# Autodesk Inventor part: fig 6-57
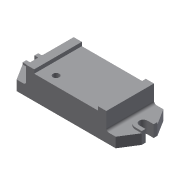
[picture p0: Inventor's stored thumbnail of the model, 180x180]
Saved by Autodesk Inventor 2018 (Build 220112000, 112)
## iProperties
Shininess: 77.0
Angle Display Precision: 2
Document Length Units: 11269
Document Angle Units: 11279
Document Time Units: 11290
Document Mass Units: 11283
Document Length Units Precision: 3
Document Angle Units Precision: 2
Created: 2001-12
Part Number: fig 6-57
Document SubType Name: Modeling
Designer: Renu Muthoo
Density: 1 g/cm^3
Material: Generic
Appearance: Default
Density: 0.0
Volumn: 0.0
Area: 0.0
PropertySet Name: Model Information
Control State: 0
Master: False
Checked Out: False
Author: Renu Muthoo
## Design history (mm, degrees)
sketch "Sketch3"
  geometry: L1 (-59.119, -24.322)-(-59.119, 19.678); L2 (-59.119, 19.678)-(-46.119, 19.678); L3 (-46.119, 19.678)-(-46.119, 13.678); L4 (-46.119, 13.678)-(55.881, 13.678); L5 (55.881, 13.678)-(55.881, 19.678); L6 (55.881, 19.678)-(68.881, 19.678); L7 (68.881, 19.678)-(68.881, -24.322); L8 (68.881, -24.322)-(-59.119, -24.322)
  constraints: 16 end point, 2 equal length
  dimensions: "d10" = 13 distance of L1.end L2.end; "d11" = 102 distance of L3.end L4.end; "d13" = 44 distance between parallel lines of L2 L8; "d14" = 6 distance of L2.end L3.end
extrude "Extrusion1" new body sketch "Sketch3" distance "d15" = 76; taper "d16" = 0 deg
sketch "Sketch4"
  geometry: L1 (0, 0)-(0, 76) reference; L2 (0, 76)-(-15, 76); L3 (-15, 76)-(-31, 50.5); L4 (-31, 50.5)-(-31, 44.5); L5 (-31, 44.5)-(-21, 44.5); L6 (-21, 31.5)-(-31, 31.5); L7 (-31, 31.5)-(-31, 25.5); L8 (-31, 25.5)-(-15, 0); L9 (-15, 0)-(0, 0); L10 (128, 76)-(0, 76) reference; L11 (0, 0)-(128, 0) reference; A1 r 6.5 centre (-21, 38) between (-21, 31.5) and (-21, 44.5)
  constraints: 16 end point, 4 equal length, 3 collinear, 3 parallel, 2 perpendicular, 2 point on circle, 2 tangent, 1 centre point
  dimensions: "d17" = 13 distance between parallel lines of L6 L5; "d18" = 25 distance of L3.end L7.end; "d19" = 10 distance of L6.start L6.end; "d20" = 15 distance of L8.end L1.start; "d21" = 16 horizontal distance of L7.end L8.end
extrude "Extrusion2" join sketch "Sketch4" distance "d22" = 16; taper "d23" = 0 deg
sketch "Sketch5"
  geometry: L1 (-159, 44.5)-(-159, 50.5) reference; L2 (-149, 44.5)-(-159, 44.5) reference; L3 (-159, 31.5)-(-149, 31.5) reference; L4 (-159, 25.5)-(-159, 31.5) reference; L5 (-159, 25.5)-(-149, 25.5); L6 (-149, 50.5)-(-159, 50.5); A1 r 6.5 centre (-149, 38) between (-149, 31.5) and (-149, 44.5) reference; A2 r 12.5 centre (-149, 38) between (-149, 25.5) and (-149, 50.5)
  constraints: 4 end point, 2 point on circle, 2 tangent, 1 centre point, 1 parallel, 1 perpendicular
extrude "Extrusion3" join sketch "Sketch5" distance "d24" = 19; taper "d25" = 0 deg
workplane "Work Plane1"
mirror "Mirror1"
fillet "Fillet1" dims "d27" = 4
sketch "Sketch6"
  geometry: L1 (0, 0)-(0, 76) reference; L2 (0, 0)-(102, 0) reference; 1 further point
  dimensions: "d28" = 20 distance from line of L1 point (20, 15); "d29" = 15 distance from line of L2 point (20, 15)
hole "Hole1" sketch "Sketch6" at (20, 15) diameter "d30" = 10; stored, may be unused: countersink angle "d34" = 82 deg, drill point angle "d36" = 118 deg; dims "d31" = 6, "d32" = 4, "d33" = 2, "d35" = 15
sketch "Sketch7"
  geometry: C1 r 5 at (20, 15) reference; 3 further points
  constraints: 4 other
body "Solid1"
other parameters: "d26" = -64
